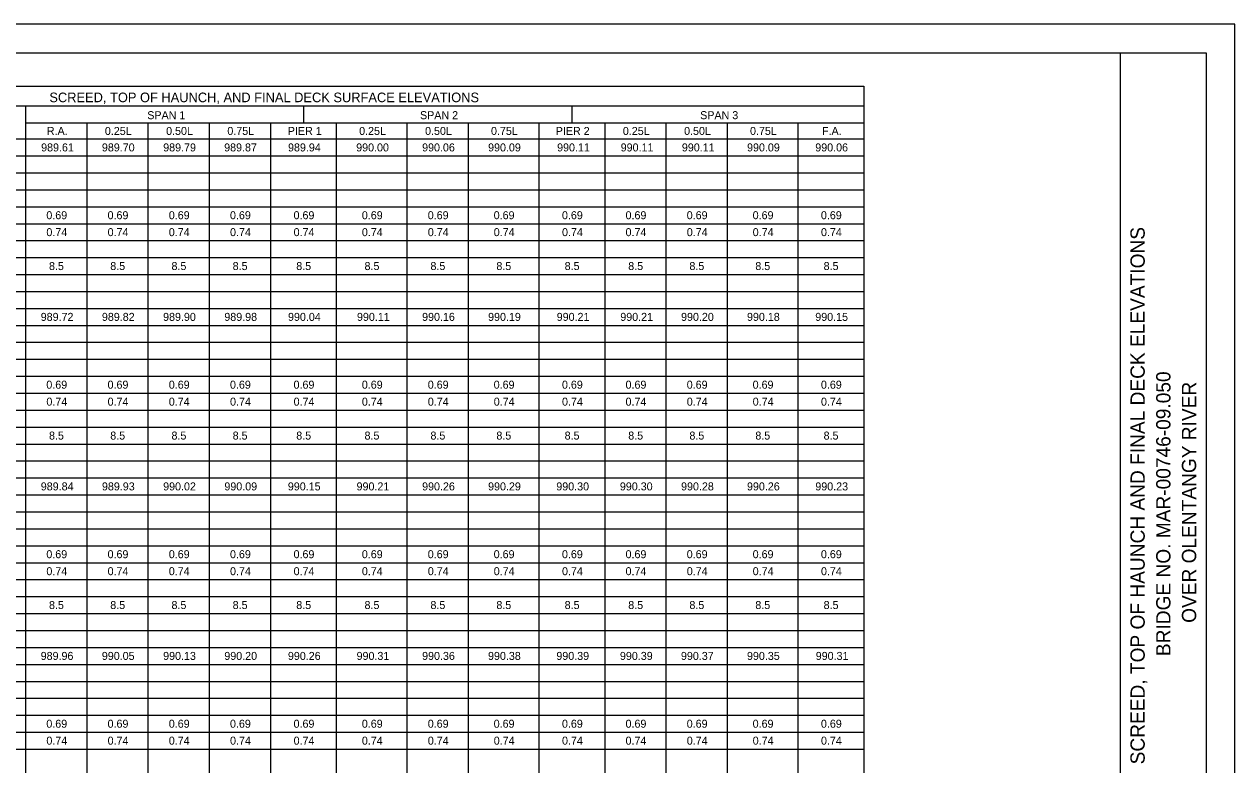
# Model space of a CAD drawing. Extents: x 0 to 34, y 0 to 22.
# Drawn here: x 12.83 to 34, y 9.05 to 22 of the extents above; entities that cross this region are included whole.
import ezdxf

# ---------------------------------------------------------------- set-up
doc = ezdxf.new("R2010")
doc.units = 0
for name, color, linetype in [('BR_P_Gen_Text', 7, 'Continuous'), ('SH_Border', 7, 'Continuous'), ('SH_Cut_Line', 7, 'Continuous'), ('SH_Data', 7, 'Continuous')]:
    doc.layers.add(name, color=color, linetype=linetype)

msp = doc.modelspace()

# ---------------------------------------------------------------- linework, layer by layer
at = {"layer": 'BR_P_Gen_Text'}
for p, q in [((6.131, 20.916), (27.51, 20.916)), ((27.51, 20.916), (27.51, 5.17)), ((6.131, 20.57), (27.51, 20.57)), ((12.851, 20.57), (12.851, 5.17)), ((17.71, 20.57), (17.71, 20.273)), ((22.404, 20.57), (22.404, 20.273)), ((12.851, 20.273), (27.51, 20.273)), ((13.921, 20.273), (13.921, 5.17)), ((14.992, 20.273), (14.992, 5.17)), ((16.063, 20.273), (16.063, 5.17)), ((17.133, 20.273), (17.133, 5.17)), ((18.286, 20.273), (18.286, 5.17)), ((19.521, 20.273), (19.521, 5.17)), ((20.592, 20.273), (20.592, 5.17)), ((21.827, 20.273), (21.827, 5.17)), ((22.98, 20.273), (22.98, 5.17)), ((24.051, 20.273), (24.051, 5.17)), ((25.121, 20.273), (25.121, 5.17)), ((26.357, 20.273), (26.357, 5.17)), ((6.131, 19.993), (27.51, 19.993)), ((6.641, 19.697), (27.51, 19.697)), ((6.641, 19.401), (27.51, 19.401)), ((6.641, 19.104), (27.51, 19.104)), ((6.641, 18.808), (27.51, 18.808)), ((6.641, 18.511), (27.51, 18.511)), ((6.641, 18.215), (27.51, 18.215)), ((6.641, 17.918), (27.51, 17.918)), ((6.641, 17.622), (27.51, 17.622)), ((6.641, 17.325), (27.51, 17.325)), ((6.131, 17.029), (27.51, 17.029)), ((6.641, 16.732), (27.51, 16.732)), ((6.641, 16.436), (27.51, 16.436)), ((6.641, 16.139), (27.51, 16.139)), ((6.641, 15.843), (27.51, 15.843)), ((6.641, 15.546), (27.51, 15.546)), ((6.641, 15.25), (27.51, 15.25)), ((6.641, 14.953), (27.51, 14.953)), ((6.641, 14.657), (27.51, 14.657)), ((6.641, 14.361), (27.51, 14.361)), ((6.131, 14.064), (27.51, 14.064)), ((6.641, 13.768), (27.51, 13.768)), ((6.641, 13.471), (27.51, 13.471)), ((6.641, 13.175), (27.51, 13.175)), ((6.641, 12.878), (27.51, 12.878)), ((6.641, 12.582), (27.51, 12.582)), ((6.641, 12.285), (27.51, 12.285)), ((6.641, 11.989), (27.51, 11.989)), ((6.641, 11.692), (27.51, 11.692)), ((6.641, 11.396), (27.51, 11.396)), ((6.131, 11.099), (27.51, 11.099)), ((6.641, 10.803), (27.51, 10.803)), ((6.641, 10.506), (27.51, 10.506)), ((6.641, 10.21), (27.51, 10.21)), ((6.641, 9.913), (27.51, 9.913)), ((6.641, 9.617), (27.51, 9.617)), ((6.641, 9.321), (27.51, 9.321))]:
    msp.add_line(p, q, dxfattribs=at)
at = {"layer": 'SH_Border'}
msp.add_line((32, 0.5), (32, 21.5), dxfattribs=at)
msp.add_lwpolyline([(1.5, 21.5), (33.5, 21.5), (33.5, 0.5), (1.5, 0.5)], close=True, dxfattribs=at)
at = {"layer": 'SH_Cut_Line'}
msp.add_lwpolyline([(0, 0), (34, 0), (34, 22), (0, 22)], close=True, dxfattribs=at)

# ---------------------------------------------------------------- texts
at = {"layer": 'BR_P_Gen_Text'}
for s, height, p in [('SCREED, TOP OF HAUNCH, AND FINAL DECK SURFACE ELEVATIONS', 0.168, (13.268, 20.636)), ('SPAN 1', 0.14, (14.98, 20.339)), ('SPAN 2', 0.14, (19.75, 20.339)), ('SPAN 3', 0.14, (24.65, 20.339)), ('R.A.', 0.14, (13.224, 20.063)), ('0.25L', 0.14, (14.239, 20.063)), ('0.50L', 0.14, (15.31, 20.063)), ('0.75L', 0.14, (16.381, 20.063)), ('PIER 1', 0.14, (17.438, 20.063)), ('0.25L', 0.14, (18.686, 20.063)), ('0.50L', 0.14, (19.839, 20.063)), ('0.75L', 0.14, (20.992, 20.063)), ('PIER 2', 0.14, (22.124, 20.063)), ('0.25L', 0.14, (23.298, 20.063)), ('0.50L', 0.14, (24.369, 20.063)), ('0.75L', 0.14, (25.522, 20.063)), ('F.A.', 0.14, (26.781, 20.063)), ('989.61', 0.14, (13.124, 19.775)), ('989.70', 0.14, (14.187, 19.775)), ('989.79', 0.14, (15.259, 19.775)), ('989.87', 0.14, (16.325, 19.775)), ('989.94', 0.14, (17.442, 19.775)), ('990.00', 0.14, (18.634, 19.775)), ('990.06', 0.14, (19.787, 19.775)), ('990.09', 0.14, (20.941, 19.775)), ('990.11', 0.14, (22.148, 19.775)), ('990.11', 0.14, (23.26, 19.775)), ('990.11', 0.14, (24.33, 19.775)), ('990.09', 0.14, (25.47, 19.775)), ('990.06', 0.14, (26.663, 19.775)), ('0.69', 0.14, (13.215, 18.589)), ('0.69', 0.14, (14.286, 18.589)), ('0.69', 0.14, (15.357, 18.589)), ('0.69', 0.14, (16.427, 18.589)), ('0.69', 0.14, (17.539, 18.589)), ('0.69', 0.14, (18.733, 18.589)), ('0.69', 0.14, (19.886, 18.589)), ('0.69', 0.14, (21.039, 18.589)), ('0.69', 0.14, (22.233, 18.589)), ('0.69', 0.14, (23.345, 18.589)), ('0.69', 0.14, (24.415, 18.589)), ('0.69', 0.14, (25.568, 18.589)), ('0.69', 0.14, (26.762, 18.589)), ('0.74', 0.14, (13.216, 18.293)), ('0.74', 0.14, (14.287, 18.293)), ('0.74', 0.14, (15.357, 18.293)), ('0.74', 0.14, (16.428, 18.293)), ('0.74', 0.14, (17.54, 18.293)), ('0.74', 0.14, (18.734, 18.293)), ('0.74', 0.14, (19.887, 18.293)), ('0.74', 0.14, (21.04, 18.293)), ('0.74', 0.14, (22.234, 18.293)), ('0.74', 0.14, (23.345, 18.293)), ('0.74', 0.14, (24.416, 18.293)), ('0.74', 0.14, (25.569, 18.293)), ('0.74', 0.14, (26.763, 18.293)), ('8.5', 0.14, (13.262, 17.7)), ('8.5', 0.14, (14.333, 17.7)), ('8.5', 0.14, (15.404, 17.7)), ('8.5', 0.14, (16.474, 17.7)), ('8.5', 0.14, (17.586, 17.7)), ('8.5', 0.14, (18.78, 17.7)), ('8.5', 0.14, (19.933, 17.7)), ('8.5', 0.14, (21.086, 17.7)), ('8.5', 0.14, (22.28, 17.7)), ('8.5', 0.14, (23.392, 17.7)), ('8.5', 0.14, (24.462, 17.7)), ('8.5', 0.14, (25.615, 17.7)), ('8.5', 0.14, (26.809, 17.7)), ('989.72', 0.14, (13.117, 16.811)), ('989.82', 0.14, (14.187, 16.811)), ('989.90', 0.14, (15.257, 16.811)), ('989.98', 0.14, (16.328, 16.811)), ('990.04', 0.14, (17.442, 16.811)), ('990.11', 0.14, (18.648, 16.811)), ('990.16', 0.14, (19.787, 16.811)), ('990.19', 0.14, (20.941, 16.811)), ('990.21', 0.14, (22.141, 16.811)), ('990.21', 0.14, (23.253, 16.811)), ('990.20', 0.14, (24.316, 16.811)), ('990.18', 0.14, (25.469, 16.811)), ('990.15', 0.14, (26.663, 16.811)), ('0.69', 0.14, (13.215, 15.625)), ('0.69', 0.14, (14.286, 15.625)), ('0.69', 0.14, (15.357, 15.625)), ('0.69', 0.14, (16.427, 15.625)), ('0.69', 0.14, (17.539, 15.625)), ('0.69', 0.14, (18.733, 15.625)), ('0.69', 0.14, (19.886, 15.625)), ('0.69', 0.14, (21.039, 15.625)), ('0.69', 0.14, (22.233, 15.625)), ('0.69', 0.14, (23.345, 15.625)), ('0.69', 0.14, (24.415, 15.625)), ('0.69', 0.14, (25.568, 15.625)), ('0.69', 0.14, (26.762, 15.625)), ('0.74', 0.14, (13.216, 15.328)), ('0.74', 0.14, (14.287, 15.328)), ('0.74', 0.14, (15.357, 15.328)), ('0.74', 0.14, (16.428, 15.328)), ('0.74', 0.14, (17.54, 15.328)), ('0.74', 0.14, (18.734, 15.328)), ('0.74', 0.14, (19.887, 15.328)), ('0.74', 0.14, (21.04, 15.328)), ('0.74', 0.14, (22.234, 15.328)), ('0.74', 0.14, (23.345, 15.328)), ('0.74', 0.14, (24.416, 15.328)), ('0.74', 0.14, (25.569, 15.328)), ('0.74', 0.14, (26.763, 15.328)), ('8.5', 0.14, (13.262, 14.735)), ('8.5', 0.14, (14.333, 14.735)), ('8.5', 0.14, (15.404, 14.735)), ('8.5', 0.14, (16.474, 14.735)), ('8.5', 0.14, (17.586, 14.735)), ('8.5', 0.14, (18.78, 14.735)), ('8.5', 0.14, (19.933, 14.735)), ('8.5', 0.14, (21.086, 14.735)), ('8.5', 0.14, (22.28, 14.735)), ('8.5', 0.14, (23.392, 14.735)), ('8.5', 0.14, (24.462, 14.735)), ('8.5', 0.14, (25.615, 14.735)), ('8.5', 0.14, (26.809, 14.735)), ('989.84', 0.14, (13.118, 13.846)), ('989.93', 0.14, (14.188, 13.846)), ('990.02', 0.14, (15.258, 13.846)), ('990.09', 0.14, (16.329, 13.846)), ('990.15', 0.14, (17.439, 13.846)), ('990.21', 0.14, (18.641, 13.846)), ('990.26', 0.14, (19.787, 13.846)), ('990.29', 0.14, (20.941, 13.846)), ('990.30', 0.14, (22.134, 13.846)), ('990.30', 0.14, (23.246, 13.846)), ('990.28', 0.14, (24.316, 13.846)), ('990.26', 0.14, (25.469, 13.846)), ('990.23', 0.14, (26.664, 13.846)), ('0.69', 0.14, (13.215, 12.66)), ('0.69', 0.14, (14.286, 12.66)), ('0.69', 0.14, (15.357, 12.66)), ('0.69', 0.14, (16.427, 12.66)), ('0.69', 0.14, (17.539, 12.66)), ('0.69', 0.14, (18.733, 12.66)), ('0.69', 0.14, (19.886, 12.66)), ('0.69', 0.14, (21.039, 12.66)), ('0.69', 0.14, (22.233, 12.66)), ('0.69', 0.14, (23.345, 12.66)), ('0.69', 0.14, (24.415, 12.66)), ('0.69', 0.14, (25.568, 12.66)), ('0.69', 0.14, (26.762, 12.66)), ('0.74', 0.14, (13.216, 12.363)), ('0.74', 0.14, (14.287, 12.363)), ('0.74', 0.14, (15.357, 12.363)), ('0.74', 0.14, (16.428, 12.363)), ('0.74', 0.14, (17.54, 12.363)), ('0.74', 0.14, (18.734, 12.363)), ('0.74', 0.14, (19.887, 12.363)), ('0.74', 0.14, (21.04, 12.363)), ('0.74', 0.14, (22.234, 12.363)), ('0.74', 0.14, (23.345, 12.363)), ('0.74', 0.14, (24.416, 12.363)), ('0.74', 0.14, (25.569, 12.363)), ('0.74', 0.14, (26.763, 12.363)), ('8.5', 0.14, (13.262, 11.771)), ('8.5', 0.14, (14.333, 11.771)), ('8.5', 0.14, (15.404, 11.771)), ('8.5', 0.14, (16.474, 11.771)), ('8.5', 0.14, (17.586, 11.771)), ('8.5', 0.14, (18.78, 11.771)), ('8.5', 0.14, (19.933, 11.771)), ('8.5', 0.14, (21.086, 11.771)), ('8.5', 0.14, (22.28, 11.771)), ('8.5', 0.14, (23.392, 11.771)), ('8.5', 0.14, (24.462, 11.771)), ('8.5', 0.14, (25.615, 11.771)), ('8.5', 0.14, (26.809, 11.771)), ('989.96', 0.14, (13.116, 10.881)), ('990.05', 0.14, (14.186, 10.881)), ('990.13', 0.14, (15.258, 10.881)), ('990.20', 0.14, (16.328, 10.881)), ('990.26', 0.14, (17.44, 10.881)), ('990.31', 0.14, (18.641, 10.881)), ('990.36', 0.14, (19.787, 10.881)), ('990.38', 0.14, (20.94, 10.881)), ('990.39', 0.14, (22.135, 10.881)), ('990.39', 0.14, (23.247, 10.881)), ('990.37', 0.14, (24.314, 10.881)), ('990.35', 0.14, (25.469, 10.881)), ('990.31', 0.14, (26.671, 10.881)), ('0.69', 0.14, (13.215, 9.695)), ('0.69', 0.14, (14.286, 9.695)), ('0.69', 0.14, (15.357, 9.695)), ('0.69', 0.14, (16.427, 9.695)), ('0.69', 0.14, (17.539, 9.695)), ('0.69', 0.14, (18.733, 9.695)), ('0.69', 0.14, (19.886, 9.695)), ('0.69', 0.14, (21.039, 9.695)), ('0.69', 0.14, (22.233, 9.695)), ('0.69', 0.14, (23.345, 9.695)), ('0.69', 0.14, (24.415, 9.695)), ('0.69', 0.14, (25.568, 9.695)), ('0.69', 0.14, (26.762, 9.695)), ('0.74', 0.14, (13.216, 9.399)), ('0.74', 0.14, (14.287, 9.399)), ('0.74', 0.14, (15.357, 9.399)), ('0.74', 0.14, (16.428, 9.399)), ('0.74', 0.14, (17.54, 9.399)), ('0.74', 0.14, (18.734, 9.399)), ('0.74', 0.14, (19.887, 9.399)), ('0.74', 0.14, (21.04, 9.399)), ('0.74', 0.14, (22.234, 9.399)), ('0.74', 0.14, (23.345, 9.399)), ('0.74', 0.14, (24.416, 9.399)), ('0.74', 0.14, (25.569, 9.399)), ('0.74', 0.14, (26.763, 9.399))]:
    msp.add_text(s, height=height, dxfattribs=at).set_placement(p)
at = {"layer": 'SH_Data'}
for s, p in [('SCREED, TOP OF HAUNCH AND FINAL DECK ELEVATIONS', (32.425, 9.054)), ('BRIDGE NO. MAR-00746-09.050', (32.875, 10.948)), ('OVER OLENTANGY RIVER', (33.325, 11.529))]:
    msp.add_text(s, height=0.25, rotation=90, dxfattribs=at).set_placement(p)

doc.saveas('drawing.dxf')
